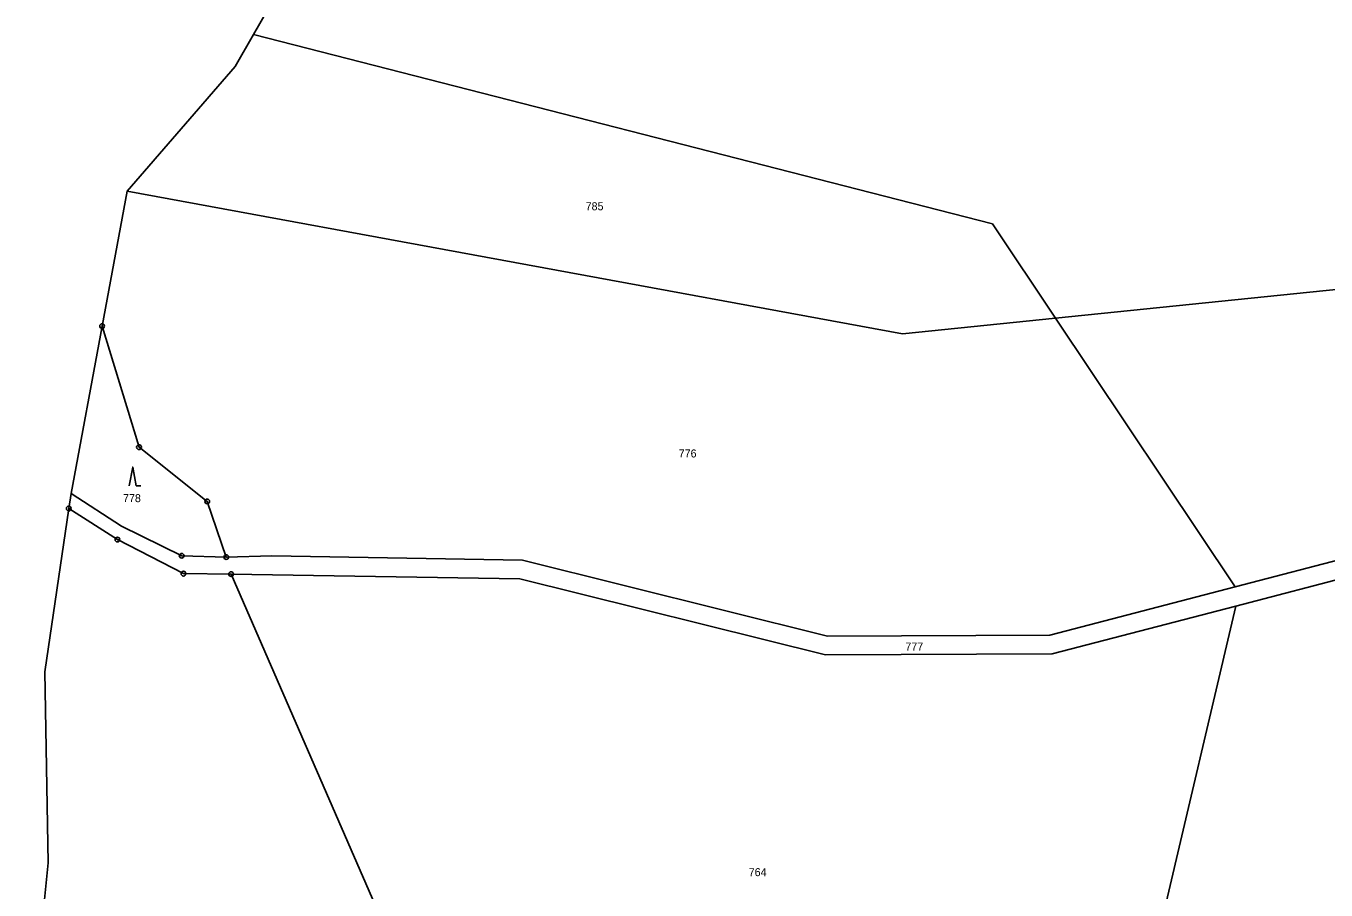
# Model space of a CAD drawing. Extents: x -719614 to -717765, y -1095834 to -1093862.
# Drawn here: x -719355.3 to -719079.2, y -1094365.9 to -1094182.4 of the extents above; entities that cross this region are included whole.
import ezdxf
from ezdxf.enums import TextEntityAlignment as Align

# ---------------------------------------------------------------- set-up
doc = ezdxf.new("R2010")
doc.units = 0
doc.header["$LTSCALE"] = 0.68
for name, color, linetype, lineweight in [('1', 7, 'Continuous', 25), ('3', 7, 'Continuous', 25), ('8', 7, 'Continuous', 25)]:
    doc.layers.add(name, color=color, linetype=linetype, lineweight=lineweight)
doc.layers.add('2', color=7, linetype='Continuous')

msp = doc.modelspace()

# ---------------------------------------------------------------- linework, layer by layer
at = {"layer": '1'}
for p, q in [((-719288.02, -1094151.12), (-719306.99, -1094184.18)), ((-719306.99, -1094184.18), (-719310.87, -1094190.94)), ((-719150.04, -1094224.41), (-719306.99, -1094184.18)), ((-719310.87, -1094190.94), (-719333.82, -1094217.45)), ((-719333.82, -1094217.45), (-719339.14, -1094246.1)), ((-719333.82, -1094217.45), (-719169.13, -1094247.77)), ((-719136.66, -1094244.44), (-719150.04, -1094224.41)), ((-719136.66, -1094244.44), (-719011.21, -1094231.58)), ((-719169.13, -1094247.77), (-719136.66, -1094244.44)), ((-719098.52, -1094301.52), (-719136.66, -1094244.44)), ((-719339.14, -1094246.1), (-719345.74, -1094281.64)), ((-719331.3, -1094271.83), (-719339.14, -1094246.1)), ((-719316.81, -1094283.36), (-719331.3, -1094271.83)), ((-719345.74, -1094281.64), (-719346.21, -1094284.86)), ((-719345.74, -1094281.64), (-719335.04, -1094288.62)), ((-719312.77, -1094295.18), (-719316.81, -1094283.36)), ((-719346.21, -1094284.86), (-719351.3, -1094319.55)), ((-719335.89, -1094291.46), (-719346.21, -1094284.86)), ((-719098.52, -1094301.52), (-719043.53, -1094287.2)), ((-719335.04, -1094288.62), (-719322.24, -1094294.89)), ((-719321.86, -1094298.7), (-719335.89, -1094291.46)), ((-719043.04, -1094291.17), (-719098.35, -1094305.6)), ((-719322.24, -1094294.89), (-719312.77, -1094295.18)), ((-719312.77, -1094295.18), (-719303.07, -1094294.94)), ((-719303.07, -1094294.94), (-719249.87, -1094295.84)), ((-719249.87, -1094295.84), (-719185.05, -1094311.96)), ((-719311.75, -1094298.79), (-719321.86, -1094298.7)), ((-719262.4, -1094412.11), (-719311.75, -1094298.79)), ((-719250.39, -1094299.83), (-719311.75, -1094298.79)), ((-719185.53, -1094315.96), (-719250.39, -1094299.83)), ((-719137.88, -1094311.77), (-719098.52, -1094301.52)), ((-719098.35, -1094305.6), (-719137.36, -1094315.77)), ((-719114.85, -1094375.65), (-719098.35, -1094305.6)), ((-719185.05, -1094311.96), (-719137.88, -1094311.77)), ((-719137.36, -1094315.77), (-719185.53, -1094315.96)), ((-719351.3, -1094319.55), (-719350.6, -1094360.12)), ((-719350.6, -1094360.12), (-719355.3, -1094406.51))]:
    msp.add_line(p, q, dxfattribs=at)
at = {"layer": '3'}
msp.add_line((-719331.88, -1094280.07), (-719330.884, -1094280.07), dxfattribs=at)
msp.add_lwpolyline([(-719331.88, -1094280.07), (-719332.63, -1094276.07), (-719333.38, -1094280.07)], dxfattribs=at)
at = {"layer": '8'}
for centre, radius in [((-719339.14, -1094246.0999), 0.5), ((-719339.14, -1094246.0999), 0.0303), ((-719331.3, -1094271.8299), 0.5), ((-719331.3, -1094271.8299), 0.0303), ((-719346.21, -1094284.8599), 0.5), ((-719316.81, -1094283.3599), 0.5), ((-719316.81, -1094283.3599), 0.0303), ((-719346.21, -1094284.8599), 0.0303), ((-719335.89, -1094291.4599), 0.5), ((-719335.89, -1094291.4599), 0.0303), ((-719322.24, -1094294.8899), 0.5), ((-719322.24, -1094294.8899), 0.0303), ((-719312.77, -1094295.1799), 0.5), ((-719312.77, -1094295.1799), 0.0303), ((-719321.86, -1094298.6999), 0.5), ((-719311.75, -1094298.7899), 0.5), ((-719321.86, -1094298.6999), 0.0303), ((-719311.75, -1094298.7899), 0.0303)]:
    msp.add_circle(centre, radius, dxfattribs=at)

# ---------------------------------------------------------------- texts
at = {"layer": '2'}
for s, p in [('785', (-719234.549, -1094221.502)), ('776', (-719214.789, -1094274.012)), ('778', (-719332.799, -1094283.512)), ('777', (-719166.649, -1094315.052)), ('764', (-719199.919, -1094362.972))]:
    msp.add_text(s, height=1.7, dxfattribs=at).set_placement(p, align=Align.CENTER)

doc.saveas('drawing.dxf')
